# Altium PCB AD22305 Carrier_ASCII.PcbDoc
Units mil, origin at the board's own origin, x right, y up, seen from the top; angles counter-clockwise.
Board outline 1000 x 1000 mil, 2 copper layers (Top Layer, Bottom Layer); 20 components, 19 nets, 82 pads, 14 vias.
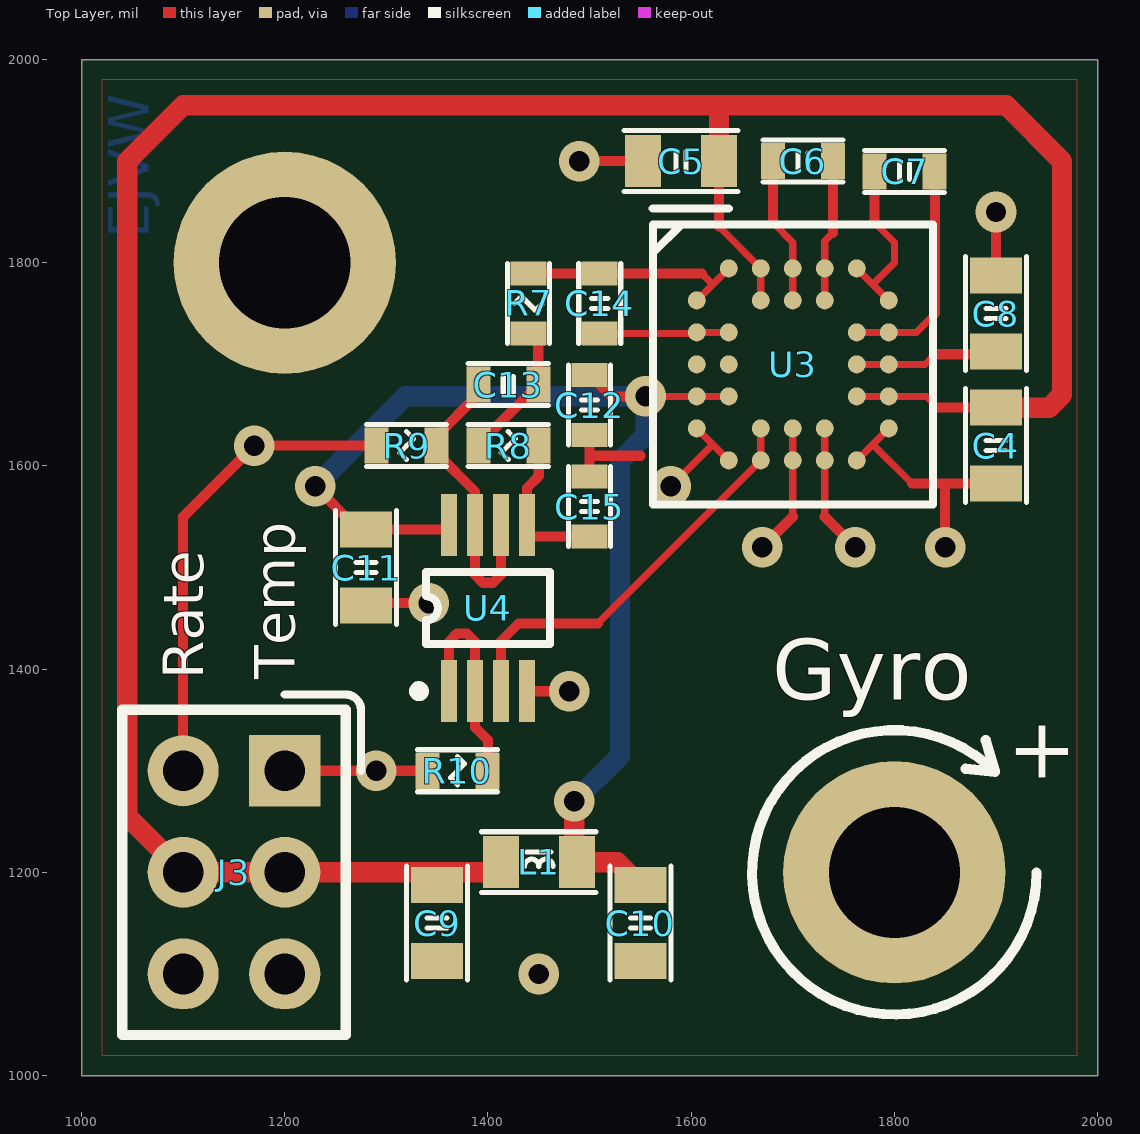
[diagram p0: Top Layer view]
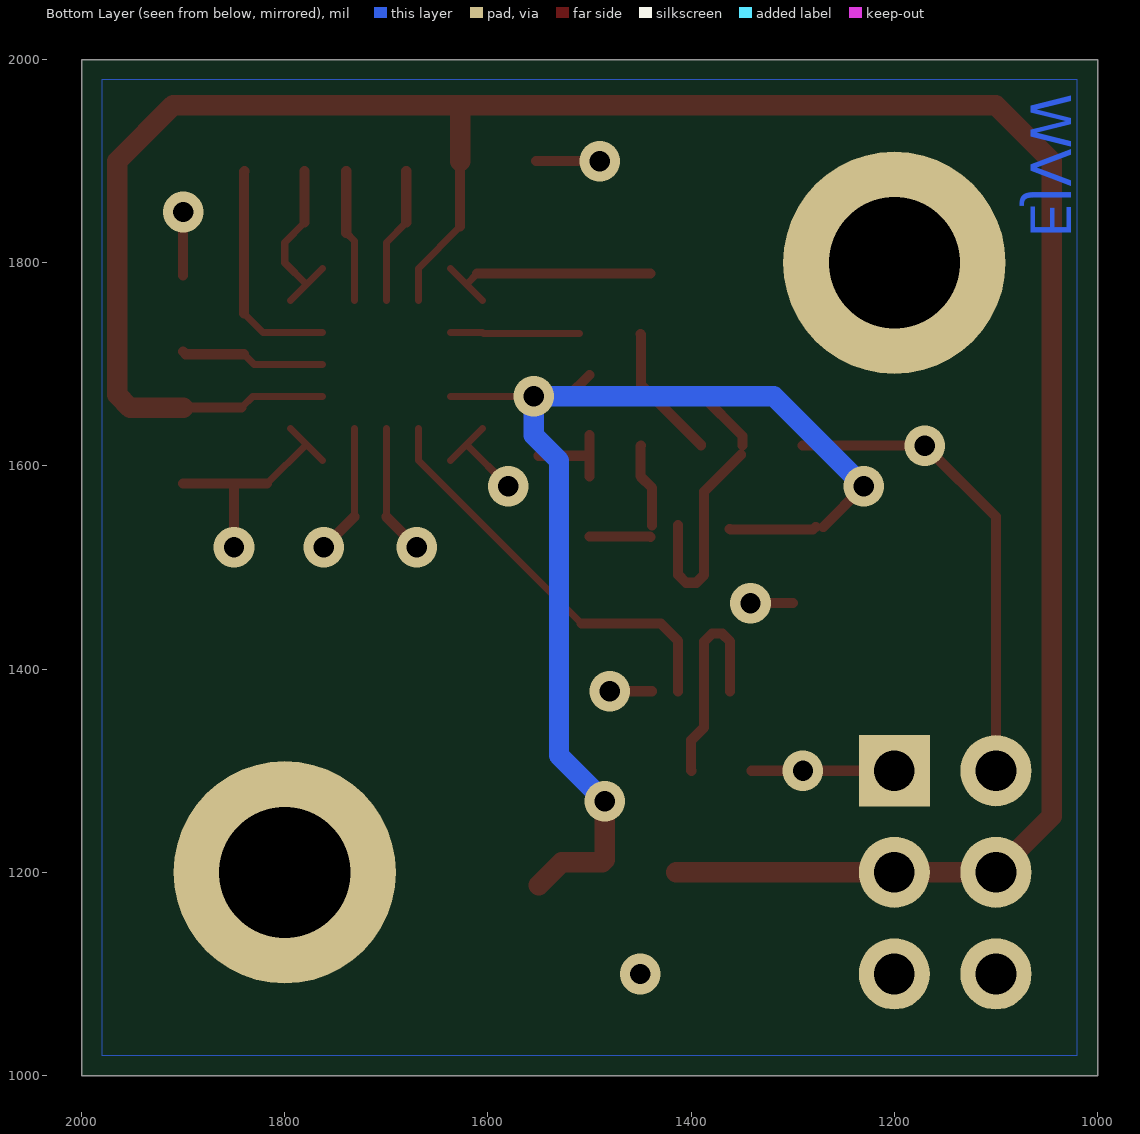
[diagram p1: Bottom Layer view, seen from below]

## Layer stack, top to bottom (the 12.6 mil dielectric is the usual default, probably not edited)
Top Layer: signal copper 1.4
Dielectric: dielectric 12.6, FR-4, Dk 4.8
Bottom Layer: signal copper 1.4

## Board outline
1000,1000 1000,2000 2000,2000 2000,1000

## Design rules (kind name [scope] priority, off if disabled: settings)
Clearance [All] p0: scope1count=1 scope1_0_kind=Board scope1_0_value=Board scope2count=1 scope2_0_kind=Board scope2_0_value=Board commentlength=0 gap=8
Clearance [All] p1: gap=8
ComponentClearance [All] p0: scope1count=1 scope1_0_kind=Board scope1_0_value=Board scope2count=1 scope2_0_kind=Board scope2_0_value=Board commentlength=0 gap=10 collisioncheckmode=3
DiffPairsRouting [All] p0: scope1count=1 scope1_0_kind=Board scope1_0_value=Board scope2count=1 scope2_0_kind=Board scope2_0_value=Board commentlength=0
FanoutControl Fanout_Default [All] p0: scope1count=1 scope1_0_kind=Board scope1_0_value=Board scope2count=1 scope2_0_kind=Board scope2_0_value=Board commentlength=30 // Fanout_Default (Default Rule)
FanoutControl Fanout_Small [All] p0 off: scope1count=1 scope1_0_kind=Board scope1_0_value=Board scope2count=1 scope2_0_kind=Board scope2_0_value=Board commentlength=84 // Protel DXP Scope 1 Expression Was: (CompPinCount < 5)   Fanout_Small (Default Rule)
FanoutControl Fanout_SOIC [All] p0 off: scope1count=1 scope1_0_kind=Board scope1_0_value=Board scope2count=1 scope2_0_kind=Board scope2_0_value=Board commentlength=71 // Protel DXP Scope 1 Expression Was: IsSOIC   Fanout_SOIC (Default Rule)
FanoutControl Fanout_LCC [All] p0 off: scope1count=1 scope1_0_kind=Board scope1_0_value=Board scope2count=1 scope2_0_kind=Board scope2_0_value=Board commentlength=69 // Protel DXP Scope 1 Expression Was: IsLCC   Fanout_LCC (Default Rule)
FanoutControl Fanout_BGA [All] p0 off: scope1count=1 scope1_0_kind=Board scope1_0_value=Board scope2count=1 scope2_0_kind=Board scope2_0_value=Board commentlength=69 // Protel DXP Scope 1 Expression Was: IsBGA   Fanout_BGA (Default Rule)
Height [All] p0: scope1count=1 scope1_0_kind=Board scope1_0_value=Board scope2count=1 scope2_0_kind=Board scope2_0_value=Board commentlength=0
HoleSize [All] p0: scope1count=1 scope1_0_kind=Board scope1_0_value=Board scope2count=1 scope2_0_kind=Board scope2_0_value=Board commentlength=0 absolutevalues=TRUE maxlimit=129 minlimit=1 maxpercent=80.000 minpercent=20.000
HoleSize [All] p1: absolutevalues=TRUE maxlimit=129 minlimit=1 maxpercent=80.000 minpercent=20.000
LayerPairs [All] p0: scope1count=1 scope1_0_kind=Board scope1_0_value=Board scope2count=1 scope2_0_kind=Board scope2_0_value=Board commentlength=0 enforce=TRUE
PasteMaskExpansion [All] p0: scope1count=1 scope1_0_kind=Board scope1_0_value=Board scope2count=1 scope2_0_kind=Board scope2_0_value=Board commentlength=0 expansion=0
PlaneClearance [All] p0: scope1count=1 scope1_0_kind=Board scope1_0_value=Board scope2count=1 scope2_0_kind=Board scope2_0_value=Board commentlength=0 clearance=20
PlaneConnect [All] p0: scope1count=1 scope1_0_kind=Board scope1_0_value=Board scope2count=1 scope2_0_kind=Board scope2_0_value=Board commentlength=0 planeconnectstyle=Relief reliefexpansion=20 reliefentries=4 reliefconductorwidth=10 reliefairgap=10
PolygonConnect [All] p0: scope1count=1 scope1_0_kind=Board scope1_0_value=Board scope2count=1 scope2_0_kind=Board scope2_0_value=Board commentlength=0 connectstyle=Relief reliefconductorwidth=10 reliefentries=4 polygonreliefangle="90 Angle"
PolygonConnect [All] p1: connectstyle=Relief reliefconductorwidth=10 reliefentries=4 polygonreliefangle="90 Angle"
RoutingCorners [All] p0: scope1count=1 scope1_0_kind=Board scope1_0_value=Board scope2count=1 scope2_0_kind=Board scope2_0_value=Board commentlength=0 cornerstyle=45-Degree minsetback=100 maxsetback=100
RoutingLayers [All] p0: scope1count=1 scope1_0_kind=Board scope1_0_value=Board scope2count=1 scope2_0_kind=Board scope2_0_value=Board commentlength=0 top layer=Automatic bottom layer=Automatic
RoutingPriority [All] p0: scope1count=1 scope1_0_kind=Board scope1_0_value=Board scope2count=1 scope2_0_kind=Board scope2_0_value=Board commentlength=0
RoutingTopology [All] p0: scope1count=1 scope1_0_kind=Board scope1_0_value=Board scope2count=1 scope2_0_kind=Board scope2_0_value=Board commentlength=0 topology=Shortest
RoutingVias [All] p0: scope1count=1 scope1_0_kind=Board scope1_0_value=Board scope2count=1 scope2_0_kind=Board scope2_0_value=Board commentlength=0 holewidth=28 width=50 viastyle="Through Hole" minholewidth=20 minwidth=40 maxholewidth=28 maxwidth=50
RoutingVias [All] p1: holewidth=28 width=50 viastyle="Through Hole" minholewidth=20 minwidth=40 maxholewidth=28 maxwidth=50
ShortCircuit [All] p0: scope1count=1 scope1_0_kind=Board scope1_0_value=Board scope2count=1 scope2_0_kind=Board scope2_0_value=Board commentlength=0 allowed=FALSE
SolderMaskExpansion [All] p0: scope1count=1 scope1_0_kind=Board scope1_0_value=Board scope2count=1 scope2_0_kind=Board scope2_0_value=Board commentlength=0 expansion=4
SolderMaskExpansion [All] p1: expansion=4
TestPointUsage [All] p0: scope1count=1 scope1_0_kind=Board scope1_0_value=Board scope2count=1 scope2_0_kind=Board scope2_0_value=Board commentlength=0 valid=0 allowmultiple=FALSE
TestPointUsage [All] p1: valid=0 allowmultiple=FALSE
Testpoint [All] p0: scope1count=1 scope1_0_kind=Board scope1_0_value=Board scope2count=1 scope2_0_kind=Board scope2_0_value=Board commentlength=0 side=15 testpointundercomponent=TRUE minsize=40 maxsize=100 preferedsize=60 minholesize=0 maxholesize=40 preferedholesize=32 testpointgrid=1 style=1023 order=0-112345678
Testpoint [All] p1: side=15 testpointundercomponent=TRUE minsize=40 maxsize=100 preferedsize=60 minholesize=0 maxholesize=40 preferedholesize=32 testpointgrid=1 style=1023 order=0-112345678
UnRoutedNet [All] p0: scope1count=1 scope1_0_kind=Board scope1_0_value=Board scope2count=1 scope2_0_kind=Board scope2_0_value=Board commentlength=0
Width [All] p0: scope1count=1 scope1_0_kind=Board scope1_0_value=Board scope2count=1 scope2_0_kind=Board scope2_0_value=Board commentlength=0 maxlimit=50 minlimit=6.99 preferedwidth=10
Width [All] p1: maxlimit=50 minlimit=6.99 preferedwidth=10
18 further rules are at their usual default settings.

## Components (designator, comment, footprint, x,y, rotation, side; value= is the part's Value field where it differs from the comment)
C4 "1.0 uF 0805  25V" C0805_C 1900,1620 r90 top
C5 "0.1uF 0805 Bypass" C0805_C 1590,1900 r0 top
C6 "0.022 uF 0603" C0603_C 1710,1900 r0 top
C7 "0.022 uF 0603" C0603_C 1810,1890 r0 top
C8 "0.1uF 0805 Bypass" C0805_C 1900,1750 r270 top
C9 "4.7uF 0805 25V X5R" C0805_C 1350,1150 r90 top
C10 "4.7uF 0805 25V X5R" C0805_C 1550,1150 r90 top
C11 "4.7uF 0805 25V X5R" C0805_C 1280,1500 r90 top
C12 "0.22 uF 0603" C0603_C 1500,1660 r90 top
C13 "0.22 uF 0603" C0603_C 1420,1680 r0 top
C14 "0.047uF 0603" C0603_C 1510,1760 r90 top
C15 "0.022 uF 0603" C0603_C 1500,1560 r270 top
J3 "THRU VERT" "H100P2x3 TSW-103-07-T-D" 1200,1300 r270 top
L1 "100 uH" L0805_C 1450,1210 r0 top
R7 "1.3k ohm 0603 1%" R0603_C 1440,1760 r270 top
R8 "16k ohm 0603 1%" R0603_C 1420,1620 r0 top
R9 "100 ohm 0603 1%" R0603_C 1320,1620 r180 top
R10 "100 ohm 0603 1%" R0603_C 1370,1300 r180 top
U3 "±250°/s Yaw Rate Gyro" BC-32 1700,1700 r0 top
U4 "AD8602 TSSOP" RM-8 1400,1460 r0 top

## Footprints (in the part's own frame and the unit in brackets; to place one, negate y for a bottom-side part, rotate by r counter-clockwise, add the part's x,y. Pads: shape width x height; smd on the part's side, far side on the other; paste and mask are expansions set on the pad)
BC-32 [mm] "Analog Devices 32-Lead Chip Scale Ball Grid Array [CSPBGA]"
  round 0.45 smd: A2(-1.6,2.4) A3(-0.8,2.4) A4(0,2.4) A5(0.8,2.4) A6(1.6,2.4) B1(-2.4,1.6) B3(-0.8,1.6) B4(0,1.6) B5(0.8,1.6) B7(2.4,1.6) C1(-2.4,0.8) C2(-1.6,0.8) C6(1.6,0.8) C7(2.4,0.8) D1(-2.4,0) D2(-1.6,0) D6(1.6,0) D7(2.4,0) E1(-2.4,-0.8) E2(-1.6,-0.8) E6(1.6,-0.8) E7(2.4,-0.8) F1(-2.4,-1.6) F3(-0.8,-1.6) F4(0,-1.6) F5(0.8,-1.6) F7(2.4,-1.6) G2(-1.6,-2.4) G3(-0.8,-2.4) G4(0,-2.4) G5(0.8,-2.4) G6(1.6,-2.4)
  silkscreen extent -3.5,-3.5 3.5,3.9
C0603_C [mm]
  rect 0.6x0.9 smd: 1(-0.75,0) 2(0.75,0)
  silkscreen extent -1,-0.53 1,0.53
C0805_C [mm]
  rect 0.9x1.3 smd: 1(-0.95,0) 2(0.95,0)
  silkscreen extent -1.43,-0.76 1.43,0.76
"H100P2x3 TSW-103-07-T-D" [mil] "Header 100mil, 2x3POS THRU VERT"
  rect 70x70 hole 40: 1(0,0)
  round 70 hole 40: 2(0,-100) 3(100,0) 4(100,-100) 5(200,0) 6(200,-100)
  silkscreen extent -75,-160 260,75
L0805_C [mm]
  rect 0.9x1.3 smd: 1(-0.95,0) 2(0.95,0)
  silkscreen extent -1.43,-0.76 1.43,0.76
R0603_C [mm]
  rect 0.6x0.9 smd: 1(-0.75,0) 2(0.75,0)
  silkscreen extent -1,-0.53 1,0.53
RM-8 [mm] "Shrink Small Outline, MSOP; 8 Leads; Body Width 3 mm; Pitch 0.65 mm"
  rect 0.4x1.55 smd: 1(-0.975,-2.075) 2(-0.325,-2.075) 3(0.325,-2.075) 4(0.975,-2.075) 5(0.975,2.075) 6(0.325,2.075) 7(-0.325,2.075) 8(-0.975,2.075)
  silkscreen extent -1.85,-2.2 1.55,0.9

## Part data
C4: "Capacitor"
C6 C7: library part "0.022 uF 0603 50V", "0.022 uF 0603 50V"
C9 C10 C11: "CERAMIC 4.7uF 25V X5R 0805"
C12: library part "0.1uF 0805 Bypass", "0.1uF 0805 Bypass"
C13: library part "0.22 uF 0603 10V", "Capacitor"
C14: library part "0.047 uF 0603 50V", "Capacitor"
C15: library part "0.033µF 0603 25V", "0.033µF 0603 25V"
J3: library part "H100 2x3 THRU VERT", "2x3 Bird Pins"
L1: library part "100 uH 0805", "100 uH 0805"
U3: library part AD22305
U4: "Op Amp 2x 8MHz Rail to Rail"

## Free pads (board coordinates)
  round 219 hole 129: MH(1200,1800) MH(1800,1200)

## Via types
v1: diameter 40, hole 20, Top Layer to Bottom Layer, 14 vias

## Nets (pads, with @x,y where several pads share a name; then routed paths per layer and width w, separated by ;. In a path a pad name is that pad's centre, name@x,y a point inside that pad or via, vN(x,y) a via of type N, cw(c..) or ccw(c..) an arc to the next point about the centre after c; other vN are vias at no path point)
+5: C4.2 C5.2 C9.2 J3.3 J3.4 L1.1 U3.A3 U3.B3 U3.E6 U3.E7 | length 2654.2
  Top Layer w7: 1627.4,1835.59 U3.A3 U3.B3 ; U3.E6 U3.E7 1831.5,1668.5 1842.6,1657.4
  Top Layer w10: 1627.4,1835.59 C5.2 ; 1842.6,1657.4 C4.2
  Top Layer w20: L1.1@1415,1200 1412.6,1200 1350,1200 J3.3 J3.4 1045,1255 1045,1900 1100,1955 1627.4,1955 ; C5.2 1627.4,1955 ; C4.2 1952.4,1657.4 1965,1670 1965,1900 1910,1955 1627.4,1955
FILTERED+5: C10.2 C11.2 C12.2 L1.2 U3.E1 U3.E2 U4.8 | length 1210.3
  Top Layer w7: v1(1555,1668.5) U3.E1 U3.E2
  Top Layer w10: v1(1230,1580) C11.2@1270,1540 ; C11.2@1277.4,1540 C11.2 1361.4,1537.4 U4.8@1362,1538 ; C12.2 1521.02,1668.5 v1(1555,1668.5)
  Top Layer w20: v1(1485,1270) 1485,1212.4 L1.2 1527.4,1210 C10.2
  Bottom Layer w20: v1(1230,1580) 1318.5,1668.5 v1(1555,1668.5) 1555,1630 1530,1605 1530,1315 v1(1485,1270)
GND: C4.1 C5.1 C8.1 C9.1 C10.1 C11.1 C12.1 C15.1 J3.5 J3.6 U3.F1 U3.F7 U3.G2 U3.G6 U4.4 | length 646.7
  Top Layer w7: v1(1580,1580) 1621.26,1621.26 ; U3.F1 1621.26,1621.26 ; U3.G2 1621.26,1621.26 ; U3.G6 U3.F7 ; 1778.74,1621.26 1817.4,1582.6
  Top Layer w10: C11.1@1300,1465 v1(1341.61,1465) ; U4.4 v1(1480,1378.31) ; v1(1490,1900) C5.1 ; C15.1 C12.1 ; 1500,1610 1550,1610 ; 1817.4,1582.6 C4.1 ; v1(1850,1520) 1850,1582.6 ; C8.1 v1(1900,1850)
  other v1: 1450,1100
NetC6_1: C6.1 U3.A4 U3.B4 | length 135.1
  Top Layer w7: 1680.47,1839.53 1700,1820 U3.A4 U3.B4
  Top Layer w10: 1680.47,1839.53 C6.1@1680.47,1890
NetC6_2: C6.2 U3.A5 U3.B5 | length 130.3
  Top Layer w7: U3.B5 U3.A5 1731.5,1821.5 1739.53,1829.53
  Top Layer w10: 1739.53,1829.53 C6.2@1739.53,1890
NetC7_1: C7.1 U3.A6 U3.B7 | length 172.7
  Top Layer w7: U3.A6 1778.74,1778.74 ; 1780.47,1839.53 1800,1820 1800,1800 1778.74,1778.74 ; U3.B7 1778.74,1778.74
  Top Layer w10: 1780.47,1839.53 C7.1
NetC7_2: C7.2 U3.C6 U3.C7 | length 224.9
  Top Layer w7: U3.C6 U3.C7 1821.5,1731.5 1840,1750
  Top Layer w10: C7.2 1840,1889.53 1840,1750
NetC8_2: C8.2 U3.D6 U3.D7 | length 142.2
  Top Layer w7: U3.D6 U3.D7 1830,1700 1840,1710
  Top Layer w10: 1840,1710 1897.4,1710 C8.2
NetC13_1: C13.1 R9.1 U4.6 U4.7 | length 280.9
  Top Layer w10: R9.1 1349.53,1629.53 C13.1@1390,1670 ; R9.1@1351,1611 1387.2,1574.8 U4.7 1387.2,1492.8 1395,1485 1405,1485 1412.8,1492.8 U4.6
NetC13_2: C13.2 R7.2 R8.1 | length 134.7
  Top Layer w10: R8.1 1390.47,1620.94 C13.2 1449.53,1729.53 R7.2@1450,1730
NetC14_1: C14.1 U3.C1 U3.C2 | length 127.4
  Top Layer w7: C14.1 1604.49,1730.47 U3.C1 U3.C2
NetC14_2: C14.2 R7.1 U3.A2 U3.B1 | length 230.3
  Top Layer w7: U3.B1 U3.A2 ; 1610.47,1789.53 1621.26,1778.74
  Top Layer w10: R7.1 C14.2 1610.47,1789.53
NetC15_2: C15.2 R8.2 U4.5 | length 143.5
  Top Layer w10: U4.5 1438.39,1578.39 1450,1590 1450,1619.53 R8.2 ; U4.5@1440,1530 1440.47,1530.47 C15.2
NetR10_1: R10.1 U4.1 U4.2 | length 213.6
  Top Layer w10: U4.1 1361.61,1427.2 1369.41,1435 1379.41,1435 1387.2,1427.2 U4.2 1387.2,1342.8 1400,1330 1400,1300.47 R10.1
NetU3_F3: U3.F3 U3.G3 U4.3 | length 410.3
  Top Layer w7: 1507.99,1445 U3.G3 U3.F3
  Top Layer w10: U4.3 1412.8,1427.8 1430,1445 1507.99,1445
RATE: J3.2 R9.2 | length 469.5
  Top Layer w10: J3.2 1100,1550 v1(1170,1620) R9.2
ST1: U3.F5 U3.G5 | length 129.4
  Top Layer w7: 1731.5,1550 U3.G5 U3.F5
  Top Layer w10: 1731.5,1550 v1(1761.5,1520)
ST2: U3.F4 U3.G4 | length 129.4
  Top Layer w7: 1700,1550 U3.G4 U3.F4
  Top Layer w10: v1(1670,1520) 1700,1550
TEMP: J3.1 R10.2 | length 140.5
  Top Layer w10: J3.1 v1(1290,1300) R10.2
pads on no net: U3.D1 U3.D2

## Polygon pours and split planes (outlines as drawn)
GND on Top Layer "Bottom Layer-No Net" (solid, remove dead copper, pour order 1000): 1980,1020 1980,1980 1020,1980 1020,1020 1980,1020
GND on Bottom Layer "Bottom Layer-No Net" (solid, remove dead copper, pour order 1000): 1020,1020 1020,1980 1980,1980 1980,1020 1020,1020

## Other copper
Bottom Layer:
  text "EJVW" at 1066,1824 h40 r90

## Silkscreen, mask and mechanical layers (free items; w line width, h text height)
Top Overlay:
  lines w10: 1870,1302 1898.99,1298.99 ; 1890,1330 1898.99,1298.99 ; 1940,1200 cw(c1800,1200) 1898.99,1298.99
  text "Rate" at 1120,1390 h40 r90
  text "Temp" at 1210,1390 h40 r90
  text "Gyro" at 1680,1370 h60
  text "+" at 1911,1293 h60
Mechanical 1:
  lines w1.67: 3819.96,2968.52 7706.14,2968.52 ; 5455.02,879.67 5455.02,2955.18
  lines w8: 1000,1000 1000,2000 2000,2000 2000,1000 1000,1000
  text "C" at 3846.6,3000 h148.77
  text "o" at 3946.63,3000 h148.77
  text "n" at 4023.31,3000 h148.77
  text "s" at 4100,3000 h148.77
  text "t" at 4170.02,3000 h148.77
  text "r" at 4208.36,3000 h148.77
  text "u" at 4255.04,3000 h148.77
  text "c" at 4331.72,3000 h148.77
  text "t" at 4401.74,3000 h148.77
  text "i" at 4440.08,3000 h148.77
  text "o" at 4470.09,3000 h148.77
  text "n" at 4546.78,3000 h148.77
  text "P" at 1016.13,2871.71 h148.77
  text "r" at 1107.82,2871.71 h148.77
  text "o" at 1154.49,2871.71 h148.77
  text "j" at 1231.18,2871.71 h148.77
  text "e" at 1262.85,2871.71 h148.77
  text "c" at 1339.54,2871.71 h148.77
  text "t" at 1409.56,2871.71 h148.77
  text "P" at 2208.29,2871.71 h148.77
  text "h" at 2299.98,2871.71 h148.77
  text "o" at 2376.66,2871.71 h148.77
  text "e" at 2453.35,2871.71 h148.77
  text "n" at 2530.03,2871.71 h148.77
  text "i" at 2606.72,2871.71 h148.77
  text "x" at 2636.72,2871.71 h148.77
  text "L" at 3846.6,2828.29 h148.77
  text "a" at 3923.29,2828.29 h148.77
  text "y" at 3999.98,2828.29 h148.77
  text "e" at 4064.99,2828.29 h148.77
  text "r" at 4141.68,2828.29 h148.77
  text "s" at 4188.36,2828.29 h148.77
  text "2" at 5488.32,2828.29 h148.77
  text "ADW22307 Carrier" at 2200,2710 h148.77
  text "B" at 1016.13,2700 h148.77
  text "o" at 1107.82,2700 h148.77
  text "a" at 1184.5,2700 h148.77
  text "r" at 1261.19,2700 h148.77
  text "d" at 1307.87,2700 h148.77
  text "F" at 3846.6,2659.92 h148.77
  text "i" at 3931.63,2659.92 h148.77
  text "n" at 3961.63,2659.92 h148.77
  text "i" at 4038.32,2659.92 h148.77
  text "s" at 4068.33,2659.92 h148.77
  text "h" at 4138.34,2659.92 h148.77
  text "e" at 4215.03,2659.92 h148.77
  text "d" at 4291.71,2659.92 h148.77
  text "T" at 4406.74,2659.92 h148.77
  text "h" at 4493.43,2659.92 h148.77
  text "i" at 4570.12,2659.92 h148.77
  text "c" at 4600.12,2659.92 h148.77
  text "k" at 4670.14,2659.92 h148.77
  text "n" at 4741.82,2659.92 h148.77
  text "e" at 4818.51,2659.92 h148.77
  text "s" at 4895.2,2659.92 h148.77
  text "s" at 4965.21,2659.92 h148.77
  text "0" at 5488.32,2659.92 h148.77
  text "6" at 5565.01,2659.92 h148.77
  text "2" at 5641.69,2659.92 h148.77
  text "+" at 5756.72,2659.92 h148.77
  text "/" at 5836.74,2659.92 h148.77
  text "-" at 5875.08,2659.92 h148.77
  text "3" at 5960.1,2659.92 h148.77
  text "0" at 6036.79,2659.92 h148.77
  text "%" at 6113.47,2659.92 h148.77
  text "R" at 1016.13,2531.63 h148.77
  text "e" at 1116.15,2531.63 h148.77
  text "v" at 1192.84,2531.63 h148.77
  text "0" at 2208.29,2531.63 h148.77
  text "." at 2284.97,2531.63 h148.77
  text "2" at 2323.31,2531.63 h148.77
  text "S" at 3846.6,2464.87 h148.77
  text "o" at 3938.29,2464.87 h148.77
  text "l" at 4014.98,2464.87 h148.77
  text "d" at 4044.99,2464.87 h148.77
  text "e" at 4121.67,2464.87 h148.77
  text "r" at 4198.36,2464.87 h148.77
  text "M" at 4283.38,2464.87 h148.77
  text "a" at 4398.41,2464.87 h148.77
  text "s" at 4475.09,2464.87 h148.77
  text "k" at 4545.11,2464.87 h148.77
  text "U" at 5488.32,2464.87 h148.77
  text "n" at 5588.34,2464.87 h148.77
  text "s" at 5665.03,2464.87 h148.77
  text "p" at 5735.05,2464.87 h148.77
  text "e" at 5811.73,2464.87 h148.77
  text "c" at 5888.42,2464.87 h148.77
  text "i" at 5958.44,2464.87 h148.77
  text "f" at 5988.44,2464.87 h148.77
  text "i" at 6028.45,2464.87 h148.77
  text "e" at 6058.46,2464.87 h148.77
  text "d" at 6135.15,2464.87 h148.77
  text "C" at 6250.17,2464.87 h148.77
  text "o" at 6350.2,2464.87 h148.77
  text "l" at 6426.88,2464.87 h148.77
  text "o" at 6456.89,2464.87 h148.77
  text "r" at 6533.58,2464.87 h148.77
  text "T" at 5488.32,2293.16 h148.77
  text "o" at 5575.01,2293.16 h148.77
  text "p" at 5651.69,2293.16 h148.77
  text "&" at 5766.72,2293.16 h148.77
  text "B" at 5896.75,2293.16 h148.77
  text "o" at 5988.44,2293.16 h148.77
  text "t" at 6065.13,2293.16 h148.77
  text "t" at 6103.47,2293.16 h148.77
  text "o" at 6141.81,2293.16 h148.77
  text "m" at 6218.5,2293.16 h148.77
  text "S" at 3846.6,2121.45 h148.77
  text "i" at 3938.29,2121.45 h148.77
  text "l" at 3968.3,2121.45 h148.77
  text "k" at 3998.31,2121.45 h148.77
  text "S" at 4108.34,2121.45 h148.77
  text "c" at 4200.02,2121.45 h148.77
  text "r" at 4270.04,2121.45 h148.77
  text "e" at 4316.72,2121.45 h148.77
  text "e" at 4393.41,2121.45 h148.77
  text "n" at 4470.09,2121.45 h148.77
  text "U" at 5488.32,2121.45 h148.77
  text "n" at 5588.34,2121.45 h148.77
  text "s" at 5665.03,2121.45 h148.77
  text "p" at 5735.05,2121.45 h148.77
  text "e" at 5811.73,2121.45 h148.77
  text "c" at 5888.42,2121.45 h148.77
  text "i" at 5958.44,2121.45 h148.77
  text "f" at 5988.44,2121.45 h148.77
  text "i" at 6028.45,2121.45 h148.77
  text "e" at 6058.46,2121.45 h148.77
  text "d" at 6135.15,2121.45 h148.77
  text "C" at 6250.17,2121.45 h148.77
  text "o" at 6350.2,2121.45 h148.77
  text "l" at 6426.88,2121.45 h148.77
  text "o" at 6456.89,2121.45 h148.77
  text "r" at 6533.58,2121.45 h148.77
  text "T" at 5488.32,1949.74 h148.77
  text "o" at 5575.01,1949.74 h148.77
  text "p" at 5651.69,1949.74 h148.77
  text "O" at 5766.72,1949.74 h148.77
  text "n" at 5875.08,1949.74 h148.77
  text "l" at 5951.77,1949.74 h148.77
  text "y" at 5981.77,1949.74 h148.77
  text "-" at 6085.13,1949.74 h148.77
  text "I" at 6170.15,1949.74 h148.77
  text "g" at 6208.5,1949.74 h148.77
  text "n" at 6285.18,1949.74 h148.77
  text "o" at 6361.87,1949.74 h148.77
  text "r" at 6438.55,1949.74 h148.77
  text "e" at 6485.23,1949.74 h148.77
  text "B" at 6600.26,1949.74 h148.77
  text "o" at 6691.95,1949.74 h148.77
  text "t" at 6768.64,1949.74 h148.77
  text "t" at 6806.98,1949.74 h148.77
  text "o" at 6845.32,1949.74 h148.77
  text "m" at 6922.01,1949.74 h148.77
  text "S" at 7078.71,1949.74 h148.77
  text "i" at 7170.4,1949.74 h148.77
  text "l" at 7200.41,1949.74 h148.77
  text "k" at 7230.42,1949.74 h148.77
  text "C" at 3846.6,1778.03 h148.77
  text "o" at 3946.63,1778.03 h148.77
  text "p" at 4023.31,1778.03 h148.77
  text "p" at 4100,1778.03 h148.77
  text "e" at 4176.69,1778.03 h148.77
  text "r" at 4253.37,1778.03 h148.77
  text "W" at 4338.39,1778.03 h148.77
  text "e" at 4476.76,1778.03 h148.77
  text "i" at 4553.44,1778.03 h148.77
  text "g" at 4583.45,1778.03 h148.77
  text "h" at 4660.14,1778.03 h148.77
  text "t" at 4736.82,1778.03 h148.77
  text "1" at 5488.32,1778.03 h148.77
  text "/" at 5565.01,1778.03 h148.77
  text "2" at 5603.35,1778.03 h148.77
  text "o" at 5718.38,1778.03 h148.77
  text "z" at 5795.06,1778.03 h148.77
  text "o" at 5900.09,1778.03 h148.77
  text "r" at 5976.77,1778.03 h148.77
  text "t" at 6061.79,1778.03 h148.77
  text "h" at 6100.14,1778.03 h148.77
  text "i" at 6176.82,1778.03 h148.77
  text "c" at 6206.83,1778.03 h148.77
  text "k" at 6276.85,1778.03 h148.77
  text "e" at 6348.53,1778.03 h148.77
  text "r" at 6425.22,1778.03 h148.77
  text "T" at 3846.6,1434.61 h148.77
  text "o" at 3933.29,1434.61 h148.77
  text "p" at 4009.98,1434.61 h148.77
  text "L" at 4125.01,1434.61 h148.77
  text "a" at 4201.69,1434.61 h148.77
  text "y" at 4278.38,1434.61 h148.77
  text "e" at 4343.39,1434.61 h148.77
  text "r" at 4420.08,1434.61 h148.77
  text "." at 5488.32,1434.61 h148.77
  text "g" at 5526.66,1434.61 h148.77
  text "t" at 5603.35,1434.61 h148.77
  text "l" at 5641.69,1434.61 h148.77
  text "G" at 3846.6,1262.91 h148.77
  text "N" at 3954.96,1262.91 h148.77
  text "D" at 4054.99,1262.91 h148.77
  text "P" at 4193.36,1262.91 h148.77
  text "l" at 4285.05,1262.91 h148.77
  text "a" at 4315.05,1262.91 h148.77
  text "n" at 4391.74,1262.91 h148.77
  text "e" at 4468.42,1262.91 h148.77
  text "." at 5488.32,1262.91 h148.77
  text "g" at 5526.66,1262.91 h148.77
  text "p" at 5603.35,1262.91 h148.77
  text "1" at 5680.03,1262.91 h148.77
  text "P" at 3846.6,1091.2 h148.77
  text "o" at 3938.29,1091.2 h148.77
  text "w" at 4014.98,1091.2 h148.77
  text "e" at 4113.34,1091.2 h148.77
  text "r" at 4190.02,1091.2 h148.77
  text "R" at 4275.04,1091.2 h148.77
  text "o" at 4375.07,1091.2 h148.77
  text "u" at 4451.75,1091.2 h148.77
  text "t" at 4528.44,1091.2 h148.77
  text "i" at 4566.78,1091.2 h148.77
  text "n" at 4596.79,1091.2 h148.77
  text "g" at 4673.47,1091.2 h148.77
  text "." at 5488.32,1091.2 h148.77
  text "g" at 5526.66,1091.2 h148.77
  text "1" at 5603.35,1091.2 h148.77
  text "B" at 3846.6,919.49 h148.77
  text "o" at 3938.29,919.49 h148.77
  text "t" at 4014.98,919.49 h148.77
  text "t" at 4053.32,919.49 h148.77
  text "o" at 4091.66,919.49 h148.77
  text "m" at 4168.35,919.49 h148.77
  text "L" at 4325.06,919.49 h148.77
  text "a" at 4401.74,919.49 h148.77
  text "y" at 4478.43,919.49 h148.77
  text "e" at 4543.44,919.49 h148.77
  text "r" at 4620.13,919.49 h148.77
  text "." at 5488.32,919.49 h148.77
  text "g" at 5526.66,919.49 h148.77
  text "b" at 5603.35,919.49 h148.77
  text "l" at 5680.03,919.49 h148.77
